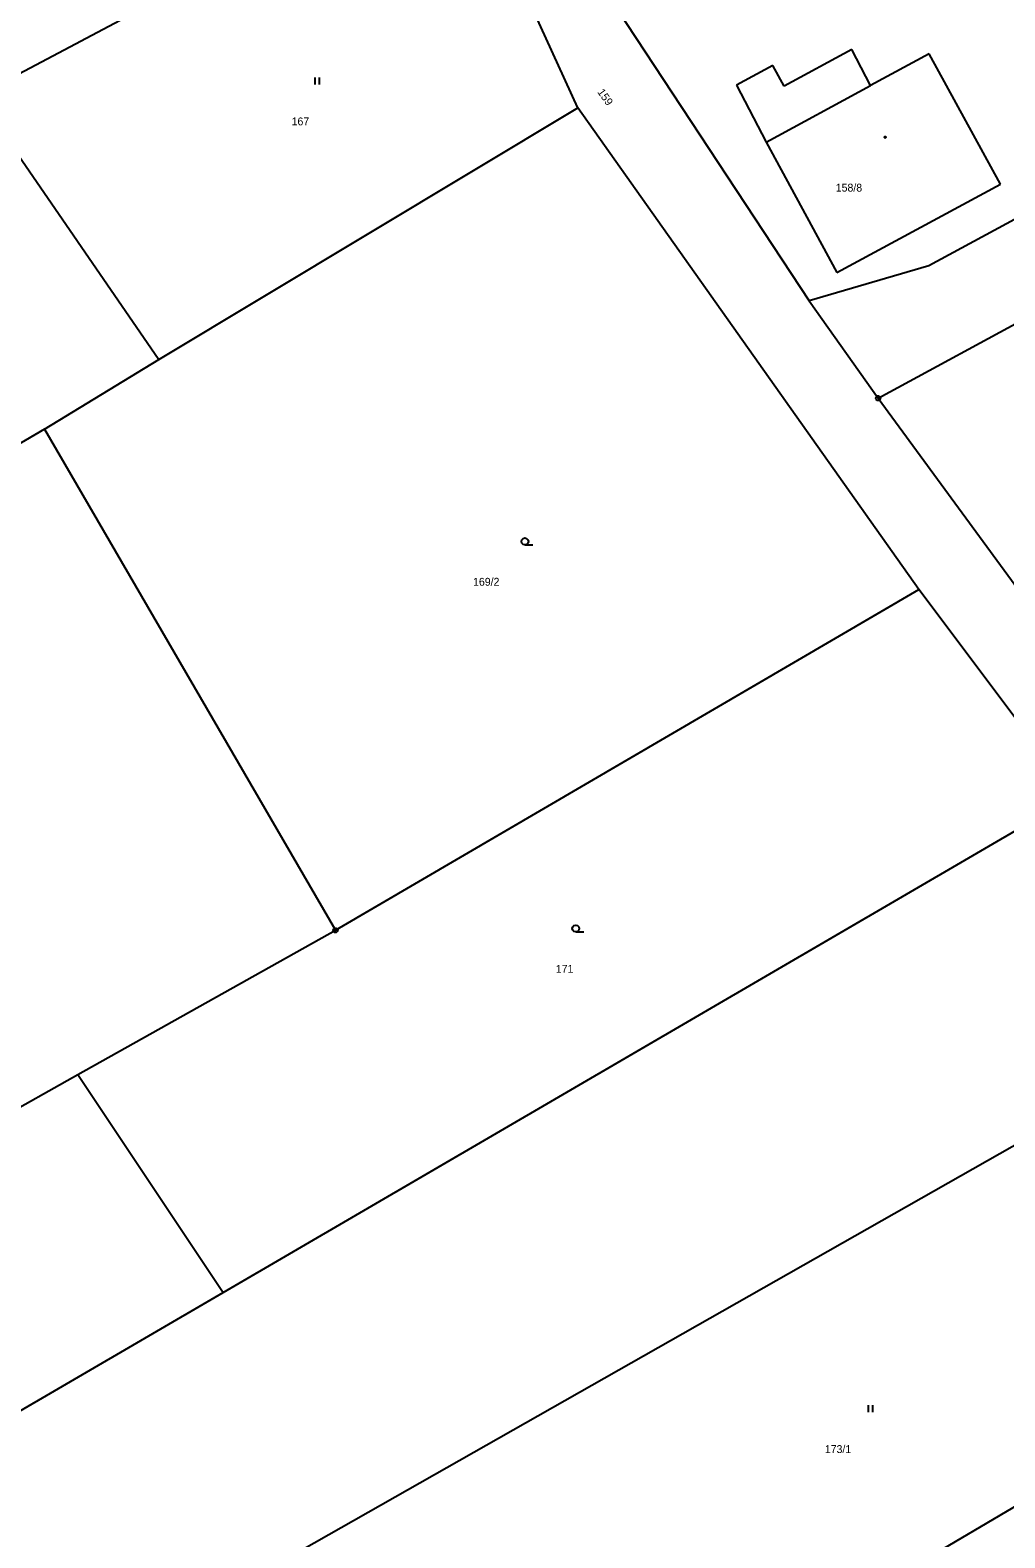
# Model space of a CAD drawing. Extents: x -871430 to -870620, y -1010094 to -1009649.
# Drawn here: x -870947.7 to -870895.2, y -1009938.3 to -1009857 of the extents above; entities that cross this region are included whole.
import ezdxf

# ---------------------------------------------------------------- set-up
doc = ezdxf.new("R2010")
doc.units = 0
for name, color, linetype in [('Vrstva 1', 7, 'Continuous'), ('Vrstva 2', 7, 'Continuous'), ('Vrstva 3', 7, 'Continuous'), ('Vrstva 4', 7, 'Continuous'), ('Vrstva 5', 7, 'Continuous'), ('Vrstva 8', 7, 'Continuous')]:
    doc.layers.add(name, color=color, linetype=linetype)

msp = doc.modelspace()

# ---------------------------------------------------------------- linework, layer by layer
at = {"layer": 'Vrstva 1'}
for p, q in [((-870950.59, -1009860.56), (-870924.77, -1009846.86)), ((-870918.22, -1009861.2), (-870924.77, -1009846.86)), ((-870917.84, -1009853.25), (-870905.75, -1009871.61)), ((-870903.45, -1009858.07), (-870907.1, -1009860.04)), ((-870902.45, -1009860), (-870903.45, -1009858.07)), ((-870907.71, -1009858.92), (-870909.68, -1009859.98)), ((-870907.1, -1009860.04), (-870907.71, -1009858.92)), ((-870899.28, -1009858.3), (-870902.45, -1009860)), ((-870878.69, -1009858.54), (-870899.31, -1009869.72)), ((-870895.45, -1009865.32), (-870899.28, -1009858.3)), ((-870950.59, -1009860.56), (-870940.81, -1009874.77)), ((-870909.68, -1009859.98), (-870908.07, -1009863.05)), ((-870940.81, -1009874.77), (-870918.22, -1009861.2)), ((-870899.84, -1009887.16), (-870918.22, -1009861.2)), ((-870908.07, -1009863.05), (-870904.26, -1009870.08)), ((-870904.26, -1009870.08), (-870895.45, -1009865.32)), ((-870902.04, -1009876.85), (-870881.26, -1009865.58)), ((-870899.31, -1009869.72), (-870905.75, -1009871.61)), ((-870905.75, -1009871.61), (-870902.04, -1009876.85)), ((-870946.97, -1009878.52), (-870940.81, -1009874.77)), ((-870902.04, -1009876.85), (-870894.31, -1009887.4)), ((-870946.97, -1009878.52), (-870960.61, -1009886.5)), ((-870946.97, -1009878.52), (-870931.29, -1009905.53)), ((-870931.29, -1009905.53), (-870899.84, -1009887.16)), ((-870891.48, -1009898.32), (-870899.84, -1009887.16)), ((-870937.35, -1009925.05), (-870891.48, -1009898.32)), ((-870945.17, -1009913.3), (-870931.29, -1009905.53)), ((-870935.49, -1009940.26), (-870881.66, -1009909.72)), ((-870952.06, -1009917.16), (-870945.17, -1009913.3)), ((-870945.17, -1009913.3), (-870937.35, -1009925.05)), ((-870924.06, -1009953.89), (-870869.59, -1009921.79)), ((-870959.69, -1009938.06), (-870937.35, -1009925.05))]:
    msp.add_line(p, q, dxfattribs=at)
at = {"layer": 'Vrstva 3'}
for p, q in [((-870932.395, -1009859.575), (-870932.395, -1009859.95)), ((-870932.145, -1009859.95), (-870932.145, -1009859.575)), ((-870902.575, -1009931.125), (-870902.575, -1009931.5)), ((-870902.325, -1009931.5), (-870902.325, -1009931.125))]:
    msp.add_line(p, q, dxfattribs=at)
for points in [[(-870921.08, -1009884.76), (-870921.175, -1009884.735), (-870921.242, -1009884.665), (-870921.268, -1009884.572), (-870921.242, -1009884.48), (-870921.175, -1009884.41), (-870921.08, -1009884.385), (-870920.985, -1009884.41), (-870920.918, -1009884.48), (-870920.892, -1009884.572), (-870920.918, -1009884.665), (-870920.985, -1009884.735), (-870921.08, -1009884.76), (-870920.642, -1009884.76)], [(-870918.34, -1009905.62), (-870918.435, -1009905.595), (-870918.502, -1009905.525), (-870918.528, -1009905.432), (-870918.502, -1009905.34), (-870918.435, -1009905.27), (-870918.34, -1009905.245), (-870918.245, -1009905.27), (-870918.178, -1009905.34), (-870918.152, -1009905.432), (-870918.178, -1009905.525), (-870918.245, -1009905.595), (-870918.34, -1009905.62), (-870917.902, -1009905.62)]]:
    msp.add_lwpolyline(points, dxfattribs=at)
at = {"layer": 'Vrstva 4'}
msp.add_line((-870908.07, -1009863.05), (-870902.45, -1009860), dxfattribs=at)
at = {"layer": 'Vrstva 5'}
msp.add_lwpolyline([(-870901.66, -1009862.748), (-870901.635, -1009862.753), (-870901.622, -1009862.775), (-870901.618, -1009862.79), (-870901.622, -1009862.812), (-870901.643, -1009862.83), (-870901.66, -1009862.832), (-870901.682, -1009862.825), (-870901.698, -1009862.81), (-870901.702, -1009862.79), (-870901.698, -1009862.768), (-870901.678, -1009862.75), (-870901.66, -1009862.748)], dxfattribs=at)
at = {"layer": 'Vrstva 8'}
for p, q in [((-870902.052, -1009876.85), (-870902.028, -1009876.85)), ((-870931.302, -1009905.53), (-870931.278, -1009905.53))]:
    msp.add_line(p, q, dxfattribs=at)
for points in [[(-870902.003, -1009876.73), (-870901.94, -1009876.778), (-870901.915, -1009876.85), (-870901.94, -1009876.922), (-870902.003, -1009876.97), (-870902.078, -1009876.97), (-870902.14, -1009876.922), (-870902.165, -1009876.85), (-870902.14, -1009876.778), (-870902.078, -1009876.73), (-870902.003, -1009876.73)], [(-870931.253, -1009905.41), (-870931.19, -1009905.458), (-870931.165, -1009905.53), (-870931.19, -1009905.602), (-870931.253, -1009905.65), (-870931.328, -1009905.65), (-870931.39, -1009905.602), (-870931.415, -1009905.53), (-870931.39, -1009905.458), (-870931.328, -1009905.41), (-870931.253, -1009905.41)]]:
    msp.add_lwpolyline(points, dxfattribs=at)

# ---------------------------------------------------------------- texts
at = {"layer": 'Vrstva 2'}
msp.add_text('159', height=0.425, rotation=305.61569, dxfattribs=at).set_placement((-870917.193, -1009860.36))
for s, p in [('167', (-870933.652, -1009862.15)), ('158/8', (-870904.322, -1009865.72)), ('169/2', (-870923.872, -1009886.96)), ('171', (-870919.412, -1009907.82)), ('173/1', (-870904.912, -1009933.7))]:
    msp.add_text(s, height=0.425, dxfattribs=at).set_placement(p)

doc.saveas('drawing.dxf')
